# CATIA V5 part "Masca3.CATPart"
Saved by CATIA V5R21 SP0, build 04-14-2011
Part number: Masca3
Bounding box of the stored display mesh (mm): x 115 to 135, y -115 to 115, z -85 to 85
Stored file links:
  C:\Users\MIRCEA\Desktop\PRRO\CATIAV5\Masca3.CATPart
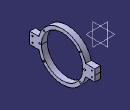
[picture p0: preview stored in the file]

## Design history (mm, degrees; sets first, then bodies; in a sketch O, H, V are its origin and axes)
Body1 (main body)
  Plane1: type Offset, RefPlane yz-plane, Offset 115
  Sketch1 on Plane1, origin (115, 0, 0), H (0, 1, 0), V (0, 0, 1)
    circle A1 centre (0, 0) radius 85
    circle A2 centre (0, 0) radius 73
    point P4 (0, 0)
    circle A3 centre (79, 0) radius 3
    circle A4 centre (63.9123, 46.435) radius 3
    circle A5 centre (-63.9123, 46.435) radius 3
    circle A6 centre (-79, 0) radius 3
    circle A7 centre (-63.9123, -46.435) radius 3
    circle A8 centre (63.9123, -46.435) radius 3
    radius A1 = 85
    radius A2 = 73
    radius A3 = 3
    radius A4 = 3
    radius A5 = 3
    radius A6 = 3
    radius A7 = 3
    radius A8 = 3
    coincidence: P4 V
  Pad1: profile Sketch1, direction (1, 0, 0), length 20
  Sketch2 on Plane1, origin (115, 0, 0), H (0, 1, 0), V (0, 0, 1)
    line L1 (115, 0) -> (115, 20)
    line L2 (115, 0) -> (115, -20)
    line L3 (115, -20) -> (80.7207, -20)
    line L4 (115, 20) -> (80.7207, 20)
    line L5 (80.7207, 20) -> (83.8008, 0)
    point P7 (83.8008, 0)
    line L6 (83.8008, 0) -> (80.7207, -20)
    line L7 (-115, 0) -> (-115, -20)
    line L8 (-115, 0) -> (-115, 20)
    line L9 (-115, 20) -> (-80.3756, 20)
    line L10 (-115, -20) -> (-80.8156, -20)
    line L11 (-80.8156, -20) -> (-83.749, 0)
    point P12 (-83.749, 0)
    line L12 (-83.749, 0) -> (-80.3756, 20)
    length L1 = 20
    length L2 = 20
    length L7 = 20
    length L8 = 20
    vertical: L1 V, L2 V, L7 V, L8 V
    horizontal: L3 H, L4 H, L9 H, L10 H
    coincidence: P7 H, P12 H
  Pad2: profile Sketch2, direction (1, 0, 0), length 20
  Plane2: type Offset, RefPlane Plane1, Offset 20
  Sketch3 on Plane2, origin (135, 0, 0), H (0, 1, 0), V (0, 0, 1)
    circle A1 centre (105, 10) radius 2
    circle A2 centre (105, -10) radius 2
    circle A3 centre (-105, 10) radius 2
    circle A4 centre (-105, -10) radius 2
    radius A1 = 2
    radius A2 = 2
    radius A3 = 2
    radius A4 = 2
  Pocket1: profile Sketch3, direction (-1, 0, 0), through (limit type 6)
